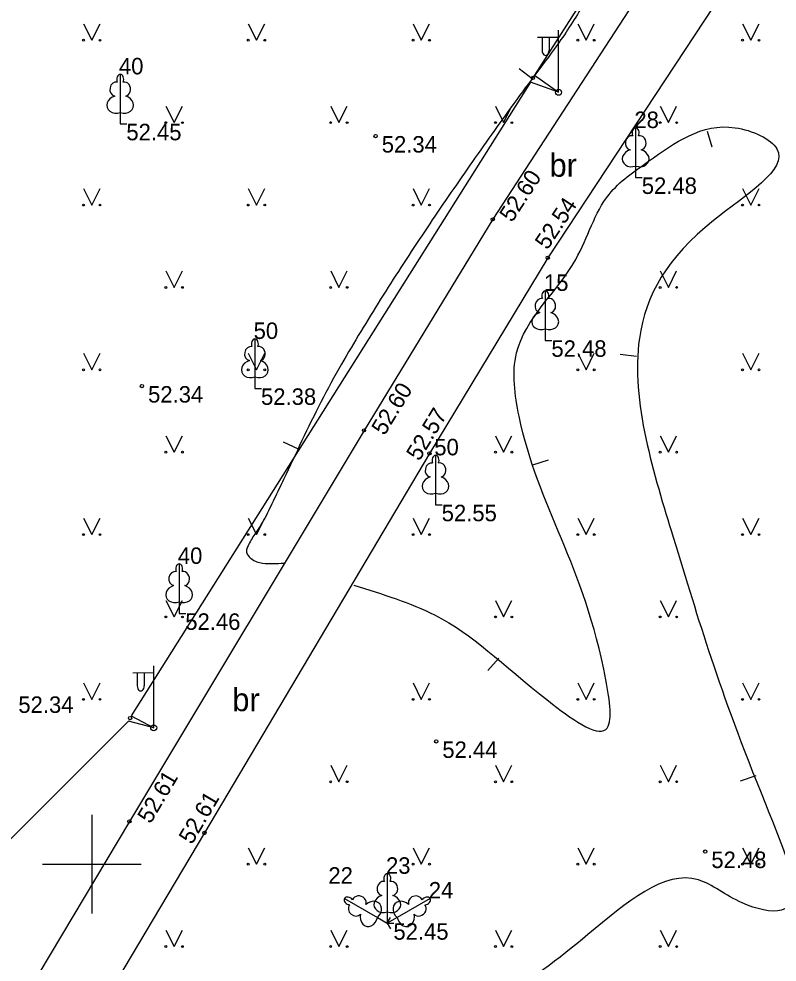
# Model space of a CAD drawing. Extents: x 619806 to 620082, y 405176 to 405386.
# Drawn here: x 619897.79 to 619920.8, y 405297.03 to 405325.65 of the extents above; entities that cross this region are included whole.
import ezdxf

# ---------------------------------------------------------------- set-up
doc = ezdxf.new("R2010")
doc.units = 0
for name, color, linetype in [('APGS_ELEM_####_####_#', 7, 'Continuous'), ('APGS_VADP_ZSPR_####_#', 7, 'Continuous'), ('CELI_CMAL_####_####_#', 7, 'Continuous'), ('CELI_CSEG_####_TKST_#', 7, 'Continuous'), ('GEOD_ELEM_####_####_#', 7, 'Continuous'), ('RELJ_AATZ_####_TKST_#', 7, 'Continuous'), ('RELJ_ELEM_####_####_#', 7, 'Continuous'), ('RELJ_HORZ_PAMT_####_#', 7, 'Continuous'), ('TERT_DIAM_####_TKST_#', 7, 'Continuous'), ('TERT_ELEM_####_####_#', 7, 'Continuous')]:
    doc.layers.add(name, color=color, linetype=linetype)

msp = doc.modelspace()

# ---------------------------------------------------------------- linework, layer by layer
at = {"layer": 'APGS_ELEM_####_####_#'}
for p, q in [((619914.167, 405323.421), (619914.167, 405325.304)), ((619914.167, 405325.088), (619913.532, 405325.083)), ((619913.667, 405325.084), (619913.667, 405324.692)), ((619913.877, 405325.086), (619913.877, 405324.692)), ((619901.88, 405304.137), (619901.88, 405306.02)), ((619901.88, 405305.804), (619901.245, 405305.799)), ((619901.38, 405305.8), (619901.38, 405305.408)), ((619901.59, 405305.802), (619901.59, 405305.408))]:
    msp.add_line(p, q, dxfattribs=at)
for centre in [(619914.167, 405323.421), (619901.88, 405304.137)]:
    msp.add_circle(centre, 0.09, dxfattribs=at)
for centre in [(619913.772, 405324.692), (619901.485, 405305.408)]:
    msp.add_ellipse(centre, major_axis=(0, 0.151), ratio=0.695971, start_param=1.570796, end_param=4.712389, dxfattribs=at)
at = {"layer": 'APGS_VADP_ZSPR_####_#'}
msp.add_lwpolyline([(619926.053, 405342.093), (619924.906, 405341.871), (619913.437, 405323.942), (619914.167, 405323.421), (619913.311, 405323.727), (619901.199, 405304.503), (619901.88, 405304.137), (619901.118, 405304.337), (619891.212, 405294.458), (619889.151, 405287.633)], dxfattribs=at)
at = {"layer": 'CELI_CMAL_####_####_#'}
for points in [[(619931.221, 405348.79), (619927.084, 405342.173), (619917.705, 405328.076), (619912.167, 405319.566), (619908.262, 405313.163), (619901.141, 405301.297), (619895.285, 405291.495)], [(619923.8, 405331.651), (619922.909, 405332.209), (619919.472, 405326.95), (619913.839, 405318.4), (619910.247, 405312.462), (619903.419, 405300.947), (619897.856, 405291.596), (619907.48, 405291.973), (619918.115, 405292.304), (619928.883, 405292.628), (619940.313, 405293.006), (619951.468, 405293.381)]]:
    msp.add_lwpolyline(points, dxfattribs=at)
at = {"layer": 'GEOD_ELEM_####_####_#'}
for p, q in [((619900, 405301.5), (619900, 405300)), ((619898.5, 405300), (619900, 405300)), ((619900, 405300), (619900, 405298.5)), ((619900, 405300), (619901.5, 405300))]:
    msp.add_line(p, q, dxfattribs=at)
at = {"layer": 'RELJ_ELEM_####_####_#'}
for centre in [(619913.386, 405323.856), (619908.615, 405322.092), (619912.167, 405319.566), (619913.839, 405318.4), (619901.523, 405314.506), (619908.262, 405313.163), (619910.247, 405312.462), (619901.164, 405304.431), (619910.453, 405303.723), (619901.141, 405301.297), (619903.419, 405300.947), (619918.617, 405300.382)]:
    msp.add_circle(centre, 0.05, dxfattribs=at)
at = {"layer": 'RELJ_HORZ_PAMT_####_#'}
for p, q in [((619912.968, 405324.14), (619913.369, 405323.841)), ((619918.831, 405321.751), (619918.688, 405322.231)), ((619916.032, 405315.472), (619916.529, 405315.418)), ((619905.811, 405312.819), (619906.263, 405312.604)), ((619913.848, 405312.257), (619913.371, 405312.108)), ((619912.016, 405305.876), (619912.352, 405306.247)), ((619919.688, 405302.526), (619920.162, 405302.686))]:
    msp.add_line(p, q, dxfattribs=at)
for points in [[(619918.742, 405329.729), (619917.612, 405329.154), (619916.499, 405328.312), (619915.614, 405327.187), (619914.833, 405325.938), (619914.442, 405325.317), (619914.031, 405324.725), (619913.331, 405323.789), (619912.64, 405322.847), (619911.31, 405320.969), (619910.015, 405319.069), (619908.767, 405317.139), (619908.164, 405316.159), (619907.577, 405315.169), (619906.955, 405314.022), (619906.379, 405312.85), (619905.821, 405311.67), (619905.539, 405311.083), (619905.25, 405310.5), (619905.107, 405310.256), (619904.948, 405310.016), (619904.743, 405309.66), (619904.718, 405309.601), (619904.698, 405309.542), (619904.72, 405309.402), (619904.84, 405309.271), (619905.01, 405309.174), (619905.183, 405309.136), (619905.828, 405309.136)], [(619907.956, 405308.464), (619910.402, 405307.562), (619913.86, 405304.951), (619915.602, 405304.09), (619915.602, 405305.597), (619912.968, 405313.592), (619912.89, 405315.511), (619914.687, 405318.349), (619915.7, 405320.324), (619916.9, 405321.328), (619919.524, 405322.347), (619920.794, 405321.7), (619918.865, 405319.529), (619916.618, 405315.954), (619917.647, 405309.917), (619920.445, 405301.831), (619920.93, 405298.602), (619919.742, 405298.823), (619918.41, 405299.521), (619915.057, 405297.864), (619909.729, 405295.803), (619908.377, 405296.58), (619903.524, 405293.78), (619899.119, 405293.642)]]:
    msp.add_spline(points, degree=3, dxfattribs=at)
at = {"layer": 'TERT_ELEM_####_####_#'}
for p, q in [((619899.75, 405325.5), (619900, 405325)), ((619900, 405325), (619900.25, 405325.5)), ((619904.75, 405325.5), (619905, 405325)), ((619905, 405325), (619905.25, 405325.5)), ((619909.75, 405325.5), (619910, 405325)), ((619910, 405325), (619910.25, 405325.5)), ((619914.75, 405325.5), (619915, 405325)), ((619915, 405325), (619915.25, 405325.5)), ((619919.75, 405325.5), (619920, 405325)), ((619920, 405325), (619920.25, 405325.5)), ((619902.25, 405323), (619902.5, 405322.5)), ((619902.5, 405322.5), (619902.75, 405323)), ((619907.25, 405323), (619907.5, 405322.5)), ((619907.5, 405322.5), (619907.75, 405323)), ((619912.25, 405323), (619912.5, 405322.5)), ((619912.5, 405322.5), (619912.75, 405323)), ((619917.25, 405323), (619917.5, 405322.5)), ((619917.5, 405322.5), (619917.75, 405323)), ((619900.864, 405322.811), (619900.864, 405322.464)), ((619900.864, 405322.464), (619901.064, 405322.464)), ((619916.506, 405321.183), (619916.506, 405320.836)), ((619916.506, 405320.836), (619916.706, 405320.836)), ((619899.75, 405320.5), (619900, 405320)), ((619900, 405320), (619900.25, 405320.5)), ((619904.75, 405320.5), (619905, 405320)), ((619905, 405320), (619905.25, 405320.5)), ((619909.75, 405320.5), (619910, 405320)), ((619910, 405320), (619910.25, 405320.5)), ((619919.75, 405320.5), (619920, 405320)), ((619920, 405320), (619920.25, 405320.5)), ((619902.25, 405318), (619902.5, 405317.5)), ((619902.5, 405317.5), (619902.75, 405318)), ((619907.25, 405318), (619907.5, 405317.5)), ((619907.5, 405317.5), (619907.75, 405318)), ((619917.25, 405318), (619917.5, 405317.5)), ((619917.5, 405317.5), (619917.75, 405318)), ((619913.763, 405316.241), (619913.763, 405315.894)), ((619913.763, 405315.894), (619913.963, 405315.894)), ((619899.75, 405315.5), (619900, 405315)), ((619900, 405315), (619900.25, 405315.5)), ((619904.75, 405315.5), (619905, 405315)), ((619905, 405315), (619905.25, 405315.5)), ((619914.75, 405315.5), (619915, 405315)), ((619915, 405315), (619915.25, 405315.5)), ((619919.75, 405315.5), (619920, 405315)), ((619920, 405315), (619920.25, 405315.5)), ((619904.951, 405314.783), (619904.951, 405314.436)), ((619904.951, 405314.436), (619905.151, 405314.436)), ((619902.25, 405313), (619902.5, 405312.5)), ((619902.5, 405312.5), (619902.75, 405313)), ((619912.25, 405313), (619912.5, 405312.5)), ((619912.5, 405312.5), (619912.75, 405313)), ((619917.25, 405313), (619917.5, 405312.5)), ((619917.5, 405312.5), (619917.75, 405313)), ((619910.434, 405311.252), (619910.434, 405310.905)), ((619910.434, 405310.905), (619910.634, 405310.905)), ((619899.75, 405310.5), (619900, 405310)), ((619900, 405310), (619900.25, 405310.5)), ((619904.75, 405310.5), (619905, 405310)), ((619905, 405310), (619905.25, 405310.5)), ((619909.75, 405310.5), (619910, 405310)), ((619910, 405310), (619910.25, 405310.5)), ((619914.75, 405310.5), (619915, 405310)), ((619915, 405310), (619915.25, 405310.5)), ((619919.75, 405310.5), (619920, 405310)), ((619920, 405310), (619920.25, 405310.5)), ((619902.25, 405308), (619902.5, 405307.5)), ((619902.5, 405307.5), (619902.75, 405308)), ((619902.652, 405307.957), (619902.652, 405307.61)), ((619912.25, 405308), (619912.5, 405307.5)), ((619912.5, 405307.5), (619912.75, 405308)), ((619917.25, 405308), (619917.5, 405307.5)), ((619917.5, 405307.5), (619917.75, 405308)), ((619902.652, 405307.61), (619902.852, 405307.61)), ((619899.75, 405305.5), (619900, 405305)), ((619900, 405305), (619900.25, 405305.5)), ((619909.75, 405305.5), (619910, 405305)), ((619910, 405305), (619910.25, 405305.5)), ((619914.75, 405305.5), (619915, 405305)), ((619915, 405305), (619915.25, 405305.5)), ((619919.75, 405305.5), (619920, 405305)), ((619920, 405305), (619920.25, 405305.5)), ((619907.25, 405303), (619907.5, 405302.5)), ((619907.5, 405302.5), (619907.75, 405303)), ((619912.25, 405303), (619912.5, 405302.5)), ((619912.5, 405302.5), (619912.75, 405303)), ((619917.25, 405303), (619917.5, 405302.5)), ((619917.5, 405302.5), (619917.75, 405303)), ((619904.75, 405300.5), (619905, 405300)), ((619905, 405300), (619905.25, 405300.5)), ((619909.75, 405300.5), (619910, 405300)), ((619910, 405300), (619910.25, 405300.5)), ((619914.75, 405300.5), (619915, 405300)), ((619915, 405300), (619915.25, 405300.5)), ((619919.75, 405300.5), (619920, 405300)), ((619920, 405300), (619920.25, 405300.5)), ((619908.969, 405298.555), (619908.969, 405298.208)), ((619908.668, 405298.381), (619908.969, 405298.208)), ((619908.969, 405298.208), (619909.069, 405298.381)), ((619909.27, 405298.381), (619908.969, 405298.208)), ((619908.969, 405298.208), (619909.169, 405298.208)), ((619908.969, 405298.208), (619909.069, 405298.035)), ((619902.25, 405298), (619902.5, 405297.5)), ((619902.5, 405297.5), (619902.75, 405298)), ((619907.25, 405298), (619907.5, 405297.5)), ((619907.5, 405297.5), (619907.75, 405298)), ((619912.25, 405298), (619912.5, 405297.5)), ((619912.5, 405297.5), (619912.75, 405298)), ((619917.25, 405298), (619917.5, 405297.5)), ((619917.5, 405297.5), (619917.75, 405298))]:
    msp.add_line(p, q, dxfattribs=at)
for points in [[(619900.864, 405323.964), (619900.864, 405322.811)], [(619900.954, 405323.732), (619900.953, 405323.733)], [(619916.506, 405322.336), (619916.506, 405321.183)], [(619916.596, 405322.104), (619916.595, 405322.105)], [(619913.763, 405317.394), (619913.763, 405316.241)], [(619913.853, 405317.162), (619913.852, 405317.163)], [(619904.951, 405315.936), (619904.951, 405314.783)], [(619905.041, 405315.704), (619905.04, 405315.705)], [(619910.434, 405312.405), (619910.434, 405311.252)], [(619910.524, 405312.173), (619910.523, 405312.174)], [(619902.652, 405309.11), (619902.652, 405307.957)], [(619902.742, 405308.878), (619902.741, 405308.879)], [(619908.969, 405299.708), (619908.969, 405298.555)], [(619909.059, 405299.476), (619909.058, 405299.477)], [(619907.67, 405298.958), (619908.668, 405298.381)], [(619907.916, 405298.919), (619907.915, 405298.919)], [(619910.268, 405298.958), (619909.27, 405298.381)], [(619910.112, 405298.764), (619910.112, 405298.766)]]:
    msp.add_lwpolyline(points, dxfattribs=at)
for centre, radius in [((619899.75, 405325), 0.028), ((619900.25, 405325), 0.0263), ((619904.75, 405325), 0.028), ((619905.25, 405325), 0.0263), ((619909.75, 405325), 0.028), ((619910.25, 405325), 0.0263), ((619914.75, 405325), 0.028), ((619915.25, 405325), 0.0263), ((619919.75, 405325), 0.028), ((619920.25, 405325), 0.0263), ((619902.25, 405322.5), 0.028), ((619902.75, 405322.5), 0.0263), ((619907.25, 405322.5), 0.028), ((619907.75, 405322.5), 0.0263), ((619912.25, 405322.5), 0.028), ((619912.75, 405322.5), 0.0263), ((619917.25, 405322.5), 0.028), ((619917.75, 405322.5), 0.0263), ((619899.75, 405320), 0.028), ((619900.25, 405320), 0.0263), ((619904.75, 405320), 0.028), ((619905.25, 405320), 0.0263), ((619909.75, 405320), 0.028), ((619910.25, 405320), 0.0263), ((619919.75, 405320), 0.028), ((619920.25, 405320), 0.0263), ((619902.25, 405317.5), 0.028), ((619902.75, 405317.5), 0.0263), ((619907.25, 405317.5), 0.028), ((619907.75, 405317.5), 0.0263), ((619917.25, 405317.5), 0.028), ((619917.75, 405317.5), 0.0263), ((619899.75, 405315), 0.028), ((619900.25, 405315), 0.0263), ((619904.75, 405315), 0.028), ((619905.25, 405315), 0.0263), ((619914.75, 405315), 0.028), ((619915.25, 405315), 0.0263), ((619919.75, 405315), 0.028), ((619920.25, 405315), 0.0263), ((619902.25, 405312.5), 0.028), ((619902.75, 405312.5), 0.0263), ((619912.25, 405312.5), 0.028), ((619912.75, 405312.5), 0.0263), ((619917.25, 405312.5), 0.028), ((619917.75, 405312.5), 0.0263), ((619899.75, 405310), 0.028), ((619900.25, 405310), 0.0263), ((619904.75, 405310), 0.028), ((619905.25, 405310), 0.0263), ((619909.75, 405310), 0.028), ((619910.25, 405310), 0.0263), ((619914.75, 405310), 0.028), ((619915.25, 405310), 0.0263), ((619919.75, 405310), 0.028), ((619920.25, 405310), 0.0263), ((619902.25, 405307.5), 0.028), ((619902.75, 405307.5), 0.0263), ((619912.25, 405307.5), 0.028), ((619912.75, 405307.5), 0.0263), ((619917.25, 405307.5), 0.028), ((619917.75, 405307.5), 0.0263), ((619899.75, 405305), 0.028), ((619900.25, 405305), 0.0263), ((619909.75, 405305), 0.028), ((619910.25, 405305), 0.0263), ((619914.75, 405305), 0.028), ((619915.25, 405305), 0.0263), ((619919.75, 405305), 0.028), ((619920.25, 405305), 0.0263), ((619907.25, 405302.5), 0.028), ((619907.75, 405302.5), 0.0263), ((619912.25, 405302.5), 0.028), ((619912.75, 405302.5), 0.0263), ((619917.25, 405302.5), 0.028), ((619917.75, 405302.5), 0.0263), ((619904.75, 405300), 0.028), ((619905.25, 405300), 0.0263), ((619909.75, 405300), 0.028), ((619910.25, 405300), 0.0263), ((619914.75, 405300), 0.028), ((619915.25, 405300), 0.0263), ((619919.75, 405300), 0.028), ((619920.25, 405300), 0.0263), ((619902.25, 405297.5), 0.028), ((619902.75, 405297.5), 0.0263), ((619907.25, 405297.5), 0.028), ((619907.75, 405297.5), 0.0263), ((619912.25, 405297.5), 0.028), ((619912.75, 405297.5), 0.0263), ((619917.25, 405297.5), 0.028), ((619917.75, 405297.5), 0.0263)]:
    msp.add_circle(centre, radius, dxfattribs=at)
for centre, major_axis, ratio, start_param, end_param in [((619900.864, 405323.814), (0, -0.15), 0.707107, 3.14537, 5.287485), ((619900.864, 405323.814), (0, -0.15), 0.707107, 0.995701, 3.137816), ((619900.736, 405323.519), (-0.039, -0.212), 0.861323, 3.141593, 6.283185), ((619900.992, 405323.519), (0.039, -0.212), 0.861323, 0, 3.141593), ((619900.774, 405323.057), (0.307, 0.095), 0.814445, 1.570796, 4.752015), ((619900.954, 405323.057), (-0.307, 0.095), 0.814445, 1.531171, 4.712389), ((619916.506, 405322.186), (0, -0.15), 0.707107, 3.14537, 5.287485), ((619916.506, 405322.186), (0, -0.15), 0.707107, 0.995701, 3.137816), ((619916.378, 405321.891), (-0.039, -0.212), 0.861323, 3.141593, 6.283185), ((619916.634, 405321.891), (0.039, -0.212), 0.861323, 0, 3.141593), ((619916.416, 405321.429), (0.307, 0.095), 0.814445, 1.570796, 4.752015), ((619916.596, 405321.429), (-0.307, 0.095), 0.814445, 1.531171, 4.712389), ((619913.763, 405317.244), (0, -0.15), 0.707107, 3.14537, 5.287485), ((619913.763, 405317.244), (0, -0.15), 0.707107, 0.995701, 3.137816), ((619913.635, 405316.949), (-0.039, -0.212), 0.861323, 3.141593, 6.283185), ((619913.891, 405316.949), (0.039, -0.212), 0.861323, 0, 3.141593), ((619913.673, 405316.487), (0.307, 0.095), 0.814445, 1.570796, 4.752015), ((619913.853, 405316.487), (-0.307, 0.095), 0.814445, 1.531171, 4.712389), ((619904.823, 405315.491), (-0.039, -0.212), 0.861323, 3.141593, 6.283185), ((619904.951, 405315.786), (0, -0.15), 0.707107, 3.14537, 5.287485), ((619904.951, 405315.786), (0, -0.15), 0.707107, 0.995701, 3.137816), ((619905.079, 405315.491), (0.039, -0.212), 0.861323, 0, 3.141593), ((619904.861, 405315.029), (0.307, 0.095), 0.814445, 1.570796, 4.752015), ((619905.041, 405315.029), (-0.307, 0.095), 0.814445, 1.531171, 4.712389), ((619910.434, 405312.255), (0, -0.15), 0.707107, 3.14537, 5.287485), ((619910.434, 405312.255), (0, -0.15), 0.707107, 0.995701, 3.137816), ((619910.306, 405311.96), (-0.039, -0.212), 0.861323, 3.141593, 6.283185), ((619910.562, 405311.96), (0.039, -0.212), 0.861323, 0, 3.141593), ((619910.344, 405311.498), (0.307, 0.095), 0.814445, 1.570796, 4.752015), ((619910.524, 405311.498), (-0.307, 0.095), 0.814445, 1.531171, 4.712389), ((619902.652, 405308.96), (0, -0.15), 0.707107, 3.14537, 5.287485), ((619902.652, 405308.96), (0, -0.15), 0.707107, 0.995701, 3.137816), ((619902.524, 405308.665), (-0.039, -0.212), 0.861323, 3.141593, 6.283185), ((619902.78, 405308.665), (0.039, -0.212), 0.861323, 0, 3.141593), ((619902.562, 405308.203), (0.307, 0.095), 0.814445, 1.570796, 4.752015), ((619902.742, 405308.203), (-0.307, 0.095), 0.814445, 1.531171, 4.712389), ((619908.969, 405299.558), (0, -0.15), 0.707107, 3.14537, 5.287485), ((619908.969, 405299.558), (0, -0.15), 0.707107, 0.995701, 3.137816), ((619908.841, 405299.263), (-0.039, -0.212), 0.861323, 3.141593, 6.283185), ((619909.097, 405299.263), (0.039, -0.212), 0.861323, 0, 3.141593), ((619908.119, 405298.847), (0.203, -0.073), 0.861323, 0, 3.141593), ((619909.819, 405298.847), (-0.203, -0.073), 0.861323, 3.141593, 6.283185), ((619907.8, 405298.883), (0.13, -0.075), 0.707107, 3.14537, 5.287485), ((619907.8, 405298.883), (0.13, -0.075), 0.707107, 0.995701, 3.137816), ((619908.5, 405298.582), (-0.236, -0.218), 0.814445, 1.531171, 4.712389), ((619908.879, 405298.801), (0.307, 0.095), 0.814445, 1.570796, 4.752015), ((619909.059, 405298.801), (-0.307, 0.095), 0.814445, 1.531171, 4.712389), ((619909.438, 405298.582), (0.236, -0.218), 0.814445, 1.570796, 4.752015), ((619910.138, 405298.883), (-0.13, -0.075), 0.707107, 3.14537, 5.287485), ((619910.138, 405298.883), (-0.13, -0.075), 0.707107, 0.995701, 3.137816), ((619907.991, 405298.624), (0.165, -0.14), 0.861323, 3.141593, 6.283185), ((619909.947, 405298.624), (-0.165, -0.14), 0.861323, 0, 3.141593), ((619908.411, 405298.427), (0.071, 0.313), 0.814445, 1.570796, 4.752015), ((619909.527, 405298.427), (-0.071, 0.313), 0.814445, 1.531171, 4.712389)]:
    msp.add_ellipse(centre, major_axis=major_axis, ratio=ratio, start_param=start_param, end_param=end_param, dxfattribs=at)

# ---------------------------------------------------------------- texts
at = {"layer": 'CELI_CSEG_####_TKST_#'}
for p in [(619913.892, 405320.859), (619904.264, 405304.642)]:
    msp.add_text('br', height=0.7, dxfattribs=at).set_placement(p)
at = {"layer": 'RELJ_AATZ_####_TKST_#'}
for s, p in [(' 52.45', (619900.864, 405321.964)), (' 52.34', (619908.615, 405321.592)), (' 52.48', (619916.506, 405320.336)), (' 52.48', (619913.763, 405315.394)), (' 52.34', (619901.523, 405314.006)), (' 52.38', (619904.951, 405313.936)), (' 52.55', (619910.434, 405310.405)), (' 52.46', (619902.652, 405307.11)), (' 52.34', (619897.586, 405304.59)), (' 52.44', (619910.453, 405303.223)), (' 52.48', (619918.617, 405299.882)), (' 52.45', (619908.969, 405297.708))]:
    msp.add_text(s, height=0.5, dxfattribs=at).set_placement(p)
for s, rotation, p in [(' 52.60', 56.9454, (619912.653, 405319.293)), (' 52.54', 56.6219, (619913.728, 405318.46)), (' 52.60', 58.6222, (619908.785, 405312.822)), (' 52.57', 58.8295, (619909.843, 405312.048)), (' 52.61', 59.3635, (619901.689, 405301.042)), (' 52.61', 59.336, (619902.944, 405300.412))]:
    msp.add_text(s, height=0.5, rotation=rotation, dxfattribs=at).set_placement(p)
at = {"layer": 'TERT_DIAM_####_TKST_#'}
for s, p in [(' 40', (619900.639, 405323.964)), (' 28', (619916.281, 405322.336)), (' 15', (619913.538, 405317.394)), (' 50', (619904.726, 405315.936)), (' 50', (619910.209, 405312.405)), (' 40', (619902.427, 405309.11)), (' 23', (619908.744, 405299.708)), (' 22', (619906.995, 405299.408)), (' 24', (619910.043, 405298.958))]:
    msp.add_text(s, height=0.5, dxfattribs=at).set_placement(p)

doc.saveas('drawing.dxf')
